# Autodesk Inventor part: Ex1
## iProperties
Author: Administrator
Created: 2001-01
Part Number: Ex1
Document SubType Name: Modeling
Designer: Administrator
Control State: 0
Master: False
Checked Out: False
PropertySet Name: Design Tracking Control
Shininess: 0.0
PropertySet Name: _Private Model Information
Density: 0.0
Volumn: 0.0
Area: 0.0
PropertySet Name: Model Information
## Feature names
1. Extrusion1
2. Extrusion2
3. Extrusion3
